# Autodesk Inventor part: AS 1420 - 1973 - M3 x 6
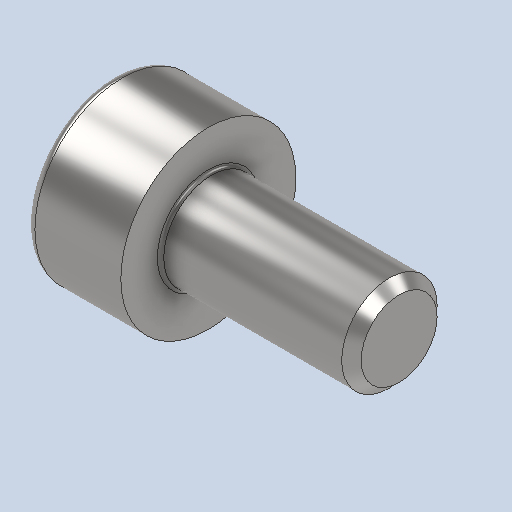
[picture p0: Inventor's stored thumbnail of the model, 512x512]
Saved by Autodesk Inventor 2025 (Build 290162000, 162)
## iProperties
Created: 2024-01
Part Number: AS 1420 - 1973 - M3 x 6
Material: Acciaio, Dolce
Description: Viti con esagono incassato metriche ISO
Document SubType Name: Modeling
Designer: Ryzen5700u
Density: 7.85 g/cm^3
Appearance: Default
Author: Ryzen5700u
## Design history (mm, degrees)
feature "Solid1"
node "Solido1"
